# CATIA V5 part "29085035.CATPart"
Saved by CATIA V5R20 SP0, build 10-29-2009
Part number: 29085035
Definition: NONE
Nomenclature: 29085035
Source: Unknown
Description: 29085035
Bounding box of the stored display mesh (mm): x -17.5 to 44.548, y -56.5 to 91.048, z -46.5 to 46.5
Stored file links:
  C:\Users\Utente\Desktop\IO LAVORO\3D X SITO CF\X SITO\PLASTICA\RF1\29085035.CATPart
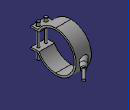
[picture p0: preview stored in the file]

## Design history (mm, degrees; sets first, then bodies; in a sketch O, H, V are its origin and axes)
Body1 "29085035" (main body)
  Solid1: solid without history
